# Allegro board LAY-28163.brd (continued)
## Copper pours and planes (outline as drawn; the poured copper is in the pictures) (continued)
GND on TOP: 39.43,11.41 44.63,11.41 46.21,9.84 46.23,9.86 46.8,9.86 48.85,11.91 48.85,12.42 50.56,14.13 51.84,14.13 56.6,9.37 56.6,9.37 57.22,8.75 57.22,8.72 58.63,8.72 60.13,10.22 60.89,10.22 62.3,8.82 62.3,7.61 61.83,7.14 54.84,7.14 54.81,7.11 52.22,7.11 51.53,6.42 49.34,6.42 48.66,7.11 38.91,7.11 38.67,7.35 38.67,10.66
GND on TOP: 44.31,12.55 44.36,12.55 46.76,14.95 47.1,14.95 49.35,17.19 50.24,17.19 50.53,16.9 50.53,16.26 48.27,13.99 48.27,13.21 45.88,10.83 45.88,10.83 44.31,12.4
GND on TOP: 69.68,2.55 69.68,4.25 65.61,8.32 65.61,12.27 69.68,16.33 69.68,20.94 68.77,21.85 68.77,23.74 69.68,24.65 69.68,25.49 61.85,33.32 61.85,46.31 63.76,48.21 72.84,48.21 72.89,48.26 72.89,48.28 80.89,48.28 80.91,48.17 80.93,48.05 80.93,28.35 80.92,28.33 80.92,5.28 78.19,2.55 ; 5 cut-outs
GND on TOP: 0.61,36.03 0.61,17.63 10.3,17.63 10.3,36.03
GND on TOP: 59.33,11.69 51.23,19.79 51.23,20.8 51.25,20.8 59.44,28.99 60.98,28.99 69.23,20.74 69.23,19.8 61.12,11.69 ; 3 cut-outs
GND on TOP: 25.62,9.66 25.85,9.43 25.85,1.36 16.77,1.36 16.71,1.3 11.92,1.3 11.92,8.95 12.62,9.66
GND on BOTTOM: 0.38,46.99 2.13,51.21 6.35,52.96 74.93,52.96 79.15,51.21 80.9,46.99 80.9,6.35 79.15,2.13 74.93,0.38 6.35,0.38 2.13,2.13 0.38,6.35 ; 4 cut-outs
GND on GND: 0.38,46.99 2.13,51.21 6.35,52.96 74.93,52.96 79.15,51.21 80.9,46.99 80.9,6.35 79.15,2.13 74.93,0.38 6.35,0.38 2.13,2.13 0.38,6.35
GND on INT_1: 4.44,0.56 4.13,0.67 3.83,0.8 0.8,3.83 0.76,3.91 0.76,49.03 4.34,52.61 7.28,52.61 7.28,36.68 9.1,34.86 9.1,14.8 7.83,13.53 7.83,9.3 11.29,5.84 15.09,5.84 17.53,3.4 17.53,1.55 16.54,0.56
GND on INT_1: 11.86,37.62 20.54,37.62 21.93,36.23 21.93,30.55 23.02,29.46 27.98,29.46 28.36,29.07 28.36,27.42 25.77,24.83 22.82,24.83 22.74,24.9 21.79,24.9 21.01,24.13 21.01,19.98 21.03,19.96 21.03,19.73 16.91,15.61 12.46,15.61 11.55,16.53 11.55,37.31
GND on INT_1: 71.24,0.58 70.9,0.92 70.9,0.59 39.51,0.59 33.18,6.92 20.45,6.92 19.09,8.29 19.09,12.63 19.8,13.34 20.09,13.34 25.8,19.05 28.08,19.05 40.26,6.88 40.82,7.45 57.61,7.45 60.32,10.16 60.32,11.45 51.6,20.17 51.6,21.44 59.46,29.29 60.7,29.29 66.88,23.11 67.01,23.23 68.86,23.23 75.81,30.18 75.81,43.24 71.95,47.1 71.95,52.51 77.38,52.51 80.55,49.35 80.68,49.01 80.79,48.66 80.79,4.68 80.65,4.24 80.47,3.8 77.48,0.81 77.18,0.69 76.89,0.58 ; 10 cut-outs
P3V3 on TOP: 36.54,7.89 36.34,8.08 36.34,9.47 36.13,9.69 36.13,14.37 35.77,14.73 35.77,15.15 33.87,15.15 32.56,16.46 26.73,16.46 24.85,18.35 24.85,19.12 24.99,19.26 33.73,19.26 35.09,17.9 39.71,17.9 39.73,17.93 41.03,17.93 42.73,16.23 42.73,15.47 42.29,15.03 37.92,15.03 37.49,14.59 37.49,12.74 38.41,11.81 38.41,8.67 37.63,7.89
P3V3 on BOTTOM: 25.81,1.39 17.26,9.95 17.26,16.96 20.71,20.41 20.71,25.56 25.58,30.43 35.63,30.43 35.7,30.5 37.12,30.5 38.44,29.18 38.44,26.04 37.53,25.14 37.53,23.17 35.18,20.82 35.15,20.82 35.15,18.26 35.69,17.72 37.63,17.72 38.94,19.03 40.58,19.03 42.8,16.81 42.8,15.83 42.64,15.67 38.1,15.67 37.5,15.06 37.5,11.35 38.59,10.26 69.72,10.26 74.45,14.99 74.45,25.23 66.64,33.04 59.19,33.04 57.28,34.95 51.25,34.95 50.7,35.5 50.7,44.84 50.94,45.09 62.49,45.09 63.22,44.35 69.25,44.35 71.56,46.67 72.2,46.67 72.76,46.11 72.76,44.38 70.25,41.87 70.25,37.05 74.54,32.76 74.54,31.1 77.3,28.34 78.96,28.34 79.78,27.52 79.78,10.31 75.14,5.67 72.31,5.67 71.06,6.92 66.61,6.92 65.35,5.67 52.85,5.67 48.58,1.39
P3V3_K64F on TOP: 38.09,14.61 42.48,14.61 43.13,13.96 43.13,11.86 42.86,11.6 38.91,11.6 37.63,12.88 37.63,14.15
P3V3_K64F on BOTTOM: 38.13,12.18 38.13,13.9 39.26,15.03 44.93,15.03 46.94,17.04 46.94,22.2 46.48,22.66 46.48,26.63 43.08,30.03 42.05,30.03 41.63,30.44 41.63,31.38 42.09,31.83 53.28,31.83 56.56,28.56 65.63,28.56 72.6,21.59 72.6,17.01 67.6,12.02 60.96,12.02 58.03,9.09 46.96,9.09 44.73,11.32 38.99,11.32
P3V3_SDA on BOTTOM: 25.97,31 20.65,36.32 19.96,36.32 16.6,39.67 15.29,39.67 13.01,37.4 8.35,37.4 7.65,38.11 7.65,39.78 11.01,43.14 20.47,43.14 22.43,41.19 30.25,41.19 30.25,41.07 29.93,40.76 29.93,40.68 30.01,40.56 30.15,40.59 30.6,40.81 31.11,40.74 32.4,40.74 32.4,40.82 33.36,40.82 33.47,40.89 33.47,41.01 33.49,41.12 33.41,41.19 40.36,41.19 41.76,42.59 41.76,43.51 40.64,44.63 40.64,45.69 40.94,45.98 46.6,45.98 47.5,45.09 47.5,43.01 47.45,42.96 46.37,42.96 46.01,42.6 46.01,40.92 48.11,38.82 48.11,35.84 47.32,35.05 45.96,35.05 45.48,35.52 45.48,37.32 43.95,38.85 39.05,38.85 37.09,36.89 37.09,35.41 35.02,33.35 30.14,33.35 30.09,33.4 27.69,31
P3V3_VREG on TOP: 29.15,13.43 32.63,13.43 33.86,14.66 34.95,14.66 35.56,14.05 35.56,11.97 34.7,11.11 34.7,7.21 34.1,6.6 26.4,6.6 26.4,10.68 27.93,10.68 29.02,11.77 29.02,13.29
P5V_K64_USB on TOP: 9.99,15.98 11.55,15.98 14.1,13.43 20.15,13.43 20.76,12.82 20.76,11.79 19.69,10.71 12.94,10.71 10.6,13.05 10.6,13.8 9.99,14.41
P5-9V_VIN_VR on TOP: 20.35,18.3 23.99,18.3 26.56,15.73 28.19,15.73 28.39,15.53 28.39,13.12 28.1,12.83 26.17,12.83 25.41,13.6 18.16,13.6 17.85,13.9 17.85,16.34 18.22,16.7 20.02,16.7 20.35,17.03
SDA_USBSHIELD on TOP: 1.13,48.32 2.9,48.32 5.4,45.82 5.4,36.93 4.55,36.07 0.96,36.07 0.47,36.57 0.47,47.66 ; 1 cut-out
SDA_USBSHIELD on BOTTOM: 0.62,47.41 3.53,47.41 3.55,47.38 3.64,47.38 5.69,45.33 5.69,43.24 4.78,42.32 4.78,36.7 4.42,36.35 1.23,36.35 0.47,37.11 0.47,47.26 0.63,47.42
SHIELD_K64USB on TOP: 1.15,17.47 4.56,17.47 4.86,17.17 4.86,15.4 5.13,15.13 5.13,7.99 2.42,5.27 1.03,5.27 0.33,5.97 0.33,16.65 ; 1 cut-out
SHIELD_K64USB on BOTTOM: 0.86,17.17 4.41,17.17 4.94,16.64 4.94,8.08 2.94,6.08 1.05,6.08 0.42,6.71 0.42,16.75 0.84,17.17
V_TGTMCU on BOTTOM: 39.74,42.22 41.23,42.22 41.5,42.49 41.5,43.1 40.11,44.49 40.11,45.65 40.63,46.17 46.88,46.17 48,45.05 48,43.88 46.4,42.28 46.4,40.6 48.56,38.44 48.56,35.57 47.4,34.42 45.77,34.42 44.53,35.65 44.53,36.76 43.26,38.04 39.15,38.04 37.72,36.61 37.72,34.89 37.57,35.04 35.32,32.79 35.3,32.79 35.3,32.26 35.5,32.05 35.5,31.15 38.69,31.15 39.77,32.22 39.79,32.22 39.99,32.43 39.99,36.55 40.47,37.02 42.3,37.02 42.97,36.35 42.97,33.98 43.88,33.08 48.37,33.08 50.04,34.75 50.04,45.63 48.54,47.13 39.66,47.13 38.84,46.31 38.84,43.07 39.72,42.2 39.74,42.22

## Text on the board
BOTTOM: 170-28163 REV D | 7 OF 10 | SECONDARY SIDE
Board Geometry/Soldermask Bottom: 8 OF 10 | SECONDARY SOLDERMASK
Ref Des/Silkscreen Bottom: 5V EXT GEN | P3V3_SDA | GND | JACK | 5V PWR | MCU | SDA RST | SW1 | RESET | C22 | C19 | C24 | SDA | R42 | R13 | R12 | R19 | R14 | R4 | RMII0_INT | VREGIN_K64 | C8 | R18 | PTA3 | PTA0 | SWD_CLK_TGTMCU | BLUETOOTH | VBAT | RMII PHY RJ45 | P5V_USB | R38 | C17 | VDDIO_ENET | C21 | P3V3_REG | P3V3_K64 | R28 | R27 | JTAG | R10 | R11 | RF MODULE | SCK | MISO | CE | CS | IRQ | MOSI | 3V3 | TX | RX | NC | ADC1 | E24 | ADC0 | [PT] | J2 | A0 | E26 | C5 | C3 | VIN | B2 | DP1 | J1 | B18 | C16 | C10 | _OUT | DAC0 | OpenSDA | K64F | USB | ADC1_SE18 | E25 | AREF | DM0 | D1 | DP0 | D3 | D2 | D0 | C4 | J3 | P3V3 | RST | 5V | C7 | C2 | C0 | A2 | C9 | B23 | DM1 | B3 | A1 | B10 | C1 | B9 | B11 | B19 | B20 | C11 | J4 | SCH | 700 | 9 OF 10 | SECONDARY SILKSCREEN | FRDM-K64F
User.Comments: 1 OF 1 | TEST PROBE | 1/1 | 1
TOP: 4 OF 10 | PRIMARY SIDE
Board Geometry/Soldermask Top: 3 OF 10 | PRIMARY SOLDERMASK
Ref Des/Silkscreen Top: SDA | USB | RESET | RST | PHY | ACCEL | K64F | RF | uSD | BT | G | R | B | INT2 | INT1 | K20 | K64 | GND | PWR 5V | RJ45 | JTAG | RGB | 2 OF 10 | PRIMARY SILKSCREEN | FRDM-K64F
GND: 5 OF 10 | GROUND PLANE
INT_1: 6 OF 10 | INTERNAL 1
XSECTION_CHART: *  SURFACE - AIR 0 MIL | *  DIELECTRIC - DRY_FILM_MASK 1 MIL | L1: TOP CONDUCTOR - 1OZ_COPPER 1.44 MIL | *  DIELECTRIC - FR-4 3 MIL | L2: GND PLANE - COPPER 1.2 MIL | *  DIELECTRIC - FR-4 4 MIL | L3: INT_1 CONDUCTOR - COPPER 1.2 MIL | *  DIELECTRIC - FR-4 49 MIL | L4: BOTTOM CONDUCTOR - COPPER_1OZ 1.44 MIL | DESIGN CROSS SECTION CHART | ___________________________ | TOTAL THICKNESS 63.28 MIL | 1-4
DIMENSION: 23. COPPER PADS FOR J4 AND J22 CAN BE SHAVED TO ALLOW .010" CLEARANCE FROM BOARD EDGE. | 22. . | INTENTIONAL SHORT IN J11 BETWEEN NETS PTA0 AND SWD_CLK_TGTMCU | 5 INTENTIONAL DANGLING VIAS IN U8 AREA. | INTENTIONAL SHORT IN J19 BETWEEN P3V3 AND P3V3_REG | INTENTIONAL SHORT IN J16 BETWEEN VREGIN_K64 AND P5V_K64_USB | INTENTIONAL SHORT IN J8 BETWEEN SWD_DIO_TGTMCU_BUF AND PTA3 | INTENTIONAL SHORT IN J5 BETWEEN NETS SDA_RST_TGTMCU_B AND SDA_RST_TGTMCU_J_B | INTENTIONAL SHORT IN J7 BETWEEN NETS P3V3_SDA AND SDA_VOUT33 | INTENTIONAL SHORT IN SH1 BETWEEN NETS P3V3 AND V_TGTMCU | INTENTIONAL SHORT IN J12 SWD_CLK_TGTMCU_BUF AND SWD_CLK_TGTMCU | INTENTIONAL SHORT IN J23 BETWEEN P3V3_K64F AND VBAT | 16 | 17 | 8 | GRID ORIGIN | PRIMARY DATUM
DISPLAY_TOP: 1 OF 10 | PASTEMASK TOP
User.5: 10 OF 10 | SECONDARY PASTEMASK
User.14: 01-23-14 | 02-06-14 | 02-26-14 | R.D.R. | B | C | D | RE-SPIN PER ECO48566 | ADD SWO TRACE | RE-SPIN PER ECO49325
User.20: FIGURE | SIZE | 10.0 | 18.0 | 28.0 | 35.0 | 40.0 | 41.0 | 47.0 | 63.0 | 125.0 | 128.0 | 34.0x30.0 | 59.0x33.0 | 91.0x32.0 | 111.0x32.0 | DRILL CHART: TOP to BOTTOM | ALL UNITS ARE IN MILS | TOLERANCE | +0.0/-10.0 | +2.0/-2.0 | +3.0/-3.0 | PLATED | NON-PLATED | QTY | 635 | 9 | 20 | 12 | 4 | 41 | 32 | 2 | 6 | 1
